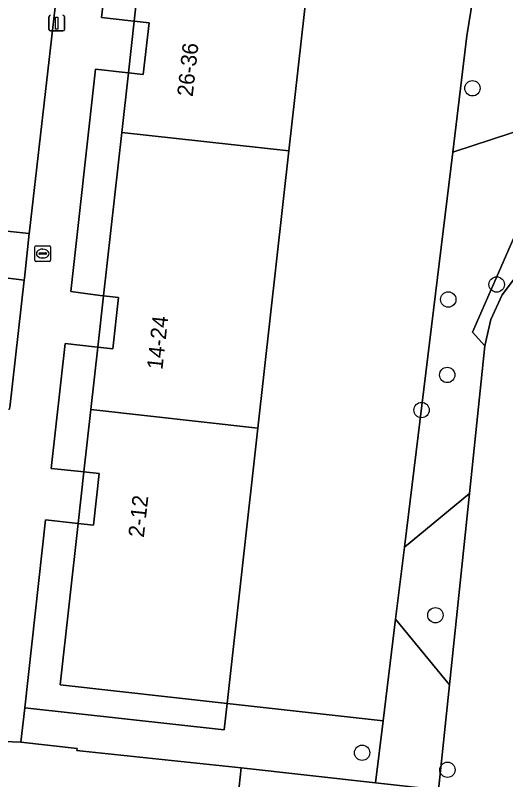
# Model space of a CAD drawing. Extents: x 161928 to 163071, y 386474 to 387428.
# Drawn here: x 162391.2 to 162422.4, y 386658.51 to 386707.21 of the extents above; entities that cross this region are included whole.
import ezdxf

# ---------------------------------------------------------------- set-up
doc = ezdxf.new("R2010")
doc.units = 0
for name, color, linetype in [('IMGEO_Boom', 7, 'Continuous'), ('IMGEO_Groenvoorziening', 7, 'Continuous'), ('IMGEO_Haag', 7, 'Continuous'), ('IMGEO_Hek', 7, 'Continuous'), ('IMGEO_Lichtmast', 7, 'Continuous'), ('IMGEO_Pand', 7, 'Continuous'), ('IMGEO_Pand_nummerreeks', 7, 'Continuous'), ('IMGEO_Rioolput', 7, 'Continuous'), ('IMGEO_Voetpad_open', 7, 'Continuous')]:
    doc.layers.add(name, color=color, linetype=linetype)

msp = doc.modelspace()

# ---------------------------------------------------------------- linework, layer by layer
at = {"layer": 'IMGEO_Boom'}
for centre in [(162420.282, 386702.561), (162421.824, 386690.06), (162418.744, 386689.105), (162418.678, 386684.298), (162417.046, 386682.063), (162417.924, 386668.993), (162413.262, 386660.232), (162418.693, 386659.146)]:
    msp.add_circle(centre, 0.489, dxfattribs=at)
at = {"layer": 'IMGEO_Groenvoorziening'}
for points in [[(162406.78, 386723.545), (162406.356, 386723.597), (162406.309, 386720.802), (162400.545, 386721.503), (162399.908, 386718.167), (162397.924, 386718.328), (162397.858, 386717.736), (162399.847, 386717.48), (162399.793, 386717.072), (162397.894, 386717.26), (162396.674, 386707.06), (162398.541, 386706.853), (162398.76, 386706.829), (162399.934, 386717.343), (162410.567, 386716.163), (162410.886, 386717.317)], [(162352.777, 386665.208), (162379.825, 386662.147), (162388.389, 386661.027), (162389.998, 386674.427), (162390.523, 386679.138), (162387.254, 386679.443), (162387.662, 386682.49), (162390.842, 386682.113), (162390.855, 386682.231), (162391.768, 386690.344), (162388.542, 386690.74), (162388.84, 386693.641), (162392.088, 386693.312), (162392.104, 386693.458), (162393.726, 386707.73), (162390.491, 386708.162), (162390.827, 386711.133), (162394.064, 386710.734), (162394.079, 386710.869), (162394.818, 386717.477), (162394.878, 386718.02), (162395.081, 386719.869), (162368.417, 386722.87)], [(162420.654, 386716.567), (162420.498, 386714.935), (162421.239, 386714.038), (162419.929, 386705.897), (162419.025, 386698.487), (162426.348, 386700.9), (162429.914, 386702.07), (162433.117, 386699.61), (162438.957, 386702.466), (162432.043, 386707.794), (162422.621, 386715.119)], [(162423.214, 386690.791), (162422.18, 386689.408), (162421.457, 386687.841), (162421.075, 386686.157), (162420.097, 386676.753), (162418.828, 386664.56), (162418.132, 386657.869), (162419.347, 386657.734), (162420.414, 386657.578), (162422.602, 386657.107)]]:
    msp.add_lwpolyline(points, dxfattribs=at)
for points in [[(162415.956, 386673.335), (162419.025, 386698.487), (162419.929, 386705.897), (162421.239, 386714.038), (162420.498, 386714.935), (162420.226, 386715.189), (162418.617, 386715.556), (162410.886, 386717.317), (162410.567, 386716.163), (162408.604, 386698.572), (162406.633, 386680.906), (162404.676, 386663.37), (162414.605, 386662.262), (162415.396, 386668.743)], [(162398.177, 386703.573), (162396.31, 386703.78), (162394.738, 386689.606), (162396.605, 386689.37), (162396.809, 386689.348), (162397.97, 386699.752), (162398.394, 386703.549)], [(162437.546, 386696.206), (162433.117, 386699.61), (162429.914, 386702.07), (162426.348, 386700.9), (162420.287, 386687.019), (162421.075, 386686.157), (162421.457, 386687.841), (162422.18, 386689.408), (162423.214, 386690.791), (162424.287, 386691.764), (162425.906, 386693.035), (162427.649, 386694.129), (162429.298, 386694.949), (162430.16, 386695.161), (162431.489, 386695.133), (162432.342, 386694.885), (162433.316, 386694.327), (162435.514, 386694.772)], [(162420.097, 386676.753), (162421.075, 386686.157), (162420.287, 386687.019), (162426.348, 386700.9), (162419.025, 386698.487), (162415.956, 386673.335)], [(162396.243, 386686.09), (162394.371, 386686.297), (162393.489, 386678.347), (162395.362, 386678.139), (162395.556, 386678.118), (162395.999, 386682.093), (162396.443, 386686.068)], [(162418.828, 386664.56), (162420.097, 386676.753), (162415.956, 386673.335), (162415.396, 386668.743)], [(162395, 386674.859), (162393.125, 386675.067), (162391.797, 386663.097), (162404.487, 386661.681), (162404.676, 386663.37), (162394.042, 386664.557), (162395.19, 386674.838)], [(162418.132, 386657.869), (162418.828, 386664.56), (162415.396, 386668.743), (162414.605, 386662.262), (162414.123, 386658.314)], [(162414.605, 386662.262), (162404.676, 386663.37), (162404.487, 386661.681), (162391.797, 386663.097), (162391.553, 386660.896), (162395.131, 386660.509), (162395.102, 386660.372), (162395.484, 386660.338), (162405.564, 386659.264), (162414.123, 386658.314)]]:
    msp.add_lwpolyline(points, close=True, dxfattribs=at)
at = {"layer": 'IMGEO_Haag'}
for points in [[(162398.177, 386703.573), (162396.31, 386703.78), (162394.738, 386689.606), (162396.605, 386689.37), (162396.809, 386689.348), (162397.97, 386699.752), (162398.394, 386703.549)], [(162396.243, 386686.09), (162394.371, 386686.297), (162393.489, 386678.347), (162395.362, 386678.139), (162395.556, 386678.118), (162395.999, 386682.093), (162396.443, 386686.068)], [(162395, 386674.859), (162393.125, 386675.067), (162391.797, 386663.097), (162404.487, 386661.681), (162404.676, 386663.37), (162394.042, 386664.557), (162395.19, 386674.838)]]:
    msp.add_lwpolyline(points, close=True, dxfattribs=at)
at = {"layer": 'IMGEO_Hek'}
for points in [[(162415.956, 386673.335), (162419.025, 386698.487)], [(162415.396, 386668.743), (162415.956, 386673.335)], [(162414.605, 386662.262), (162415.396, 386668.743)], [(162404.676, 386663.37), (162414.605, 386662.262)]]:
    msp.add_lwpolyline(points, dxfattribs=at)
at = {"layer": 'IMGEO_Lichtmast'}
for p, q in [((162393.339, 386706.311), (162393.339, 386707.111)), ((162393.339, 386707.111), (162393.339, 386706.311)), ((162394.329, 386707.111), (162394.329, 386706.311)), ((162394.329, 386706.311), (162394.329, 386707.111)), ((162394.229, 386706.211), (162393.439, 386706.211)), ((162393.439, 386706.211), (162394.229, 386706.211))]:
    msp.add_line(p, q, dxfattribs=at)
msp.add_lwpolyline([(162393.759, 386707.086), (162393.909, 386707.086), (162393.909, 386706.336), (162393.759, 386706.336), (162393.759, 386707.086)], dxfattribs=at)
for centre, start, end in [((162393.439, 386707.111), 90, 180), ((162393.439, 386707.111), 90, 180), ((162394.229, 386707.111), 0, 90), ((162394.229, 386707.111), 360, 90), ((162393.439, 386706.311), 180, 270), ((162393.439, 386706.311), 180, 270), ((162394.229, 386706.311), 270, 0), ((162394.229, 386706.311), 270, 0)]:
    msp.add_arc(centre, 0.1, start, end, dxfattribs=at)
at = {"layer": 'IMGEO_Pand'}
for points in [[(162397.97, 386699.752), (162408.604, 386698.572), (162410.567, 386716.163), (162399.934, 386717.343), (162398.76, 386706.829), (162399.704, 386706.725), (162399.341, 386703.445), (162398.394, 386703.549)], [(162408.604, 386698.572), (162397.97, 386699.752), (162396.809, 386689.348), (162397.769, 386689.242), (162397.406, 386685.962), (162396.443, 386686.068), (162395.999, 386682.093), (162406.633, 386680.906)], [(162406.633, 386680.906), (162395.999, 386682.093), (162395.556, 386678.118), (162396.526, 386678.011), (162396.163, 386674.731), (162395.19, 386674.838), (162394.042, 386664.557), (162404.676, 386663.37)]]:
    msp.add_lwpolyline(points, close=True, dxfattribs=at)
at = {"layer": 'IMGEO_Rioolput'}
for p, q in [((162392.442, 386691.605), (162392.442, 386692.457)), ((162392.517, 386692.531), (162393.369, 386692.531)), ((162393.443, 386692.457), (162393.443, 386691.605)), ((162392.701, 386692.025), (162392.701, 386692.037)), ((162393.139, 386691.988), (162392.741, 386691.988)), ((162392.744, 386692.074), (162393.142, 386692.074)), ((162392.93, 386692.311), (162392.955, 386692.311)), ((162393.185, 386692.037), (162393.185, 386692.025)), ((162393.369, 386691.531), (162392.517, 386691.531)), ((162392.953, 386691.751), (162392.928, 386691.751))]:
    msp.add_line(p, q, dxfattribs=at)
for points in [[(162392.442, 386691.605), (162392.442, 386692.457)], [(162392.517, 386692.531), (162393.369, 386692.531)], [(162393.443, 386692.457), (162393.443, 386691.605)], [(162393.369, 386691.531), (162392.517, 386691.531)]]:
    msp.add_lwpolyline(points, dxfattribs=at)
for centre, radius, start, end in [((162392.519, 386692.455), 0.0765, 91.552, 178.448), ((162392.519, 386692.455), 0.0765, 91.552, 178.448), ((162393.367, 386692.455), 0.0765, 1.552, 88.448), ((162393.367, 386692.455), 0.0765, 1.552, 88.448), ((162392.741, 386692.034), 0.0403, 85.8775, 175.7526), ((162392.738, 386692.024), 0.0366, 178.938, 274.7102), ((162393.142, 386692.031), 0.043, 264.8664, 352.4533), ((162393.146, 386692.036), 0.0386, 1.7309, 96.639), ((162392.519, 386691.607), 0.0765, 181.552, 268.448), ((162392.519, 386691.607), 0.0765, 181.552, 268.448), ((162393.367, 386691.607), 0.0765, 271.552, 358.448), ((162393.367, 386691.607), 0.0765, 271.552, 358.448)]:
    msp.add_arc(centre, radius, start, end, dxfattribs=at)
for centre, major_axis, ratio, start_param, end_param in [((162392.929, 386692.031), (-0.387, 0.002), 0.722429, 4.712389, 7.853982), ((162392.954, 386692.031), (-0.39, 0.002), 0.717154, 1.570796, 4.712389)]:
    msp.add_ellipse(centre, major_axis=major_axis, ratio=ratio, start_param=start_param, end_param=end_param, dxfattribs=at)
at = {"layer": 'IMGEO_Voetpad_open'}
for points in [[(162388.389, 386661.027), (162391.553, 386660.896), (162391.797, 386663.097), (162393.125, 386675.067), (162395, 386674.859), (162395.19, 386674.838), (162395.556, 386678.118), (162395.362, 386678.139), (162393.489, 386678.347), (162394.371, 386686.297), (162396.243, 386686.09), (162396.443, 386686.068), (162396.809, 386689.348), (162396.605, 386689.37), (162394.738, 386689.606), (162396.31, 386703.78), (162398.177, 386703.573), (162398.394, 386703.549), (162398.76, 386706.829), (162398.541, 386706.853), (162396.674, 386707.06), (162397.894, 386717.26)], [(162393.726, 386707.73), (162392.104, 386693.458), (162392.088, 386693.312), (162391.783, 386690.473), (162391.768, 386690.344), (162390.855, 386682.231)], [(162405.257, 386656.292), (162405.564, 386659.264), (162395.484, 386660.338), (162395.102, 386660.372), (162395.131, 386660.509), (162391.553, 386660.896), (162388.389, 386661.027), (162379.825, 386662.147), (162352.777, 386665.208), (162348.84, 386665.689), (162345.614, 386665.927), (162340.891, 386666.503), (162325.646, 386668.198), (162310.4, 386669.893), (162306.164, 386670.355), (162303.013, 386670.566), (162298.443, 386671.239), (162265.931, 386674.909)], [(162422.602, 386657.107), (162420.414, 386657.578), (162419.347, 386657.734), (162418.132, 386657.869), (162414.123, 386658.314), (162405.564, 386659.264), (162405.257, 386656.292), (162418.483, 386654.813), (162420.192, 386654.565), (162422.714, 386654.003)]]:
    msp.add_lwpolyline(points, dxfattribs=at)
for points in [[(162398.394, 386703.549), (162399.341, 386703.445), (162399.704, 386706.725), (162398.76, 386706.829)], [(162392.088, 386693.312), (162388.84, 386693.641), (162388.542, 386690.74), (162391.768, 386690.344), (162391.783, 386690.473)], [(162396.443, 386686.068), (162397.406, 386685.962), (162397.769, 386689.242), (162396.809, 386689.348)], [(162395.19, 386674.838), (162396.163, 386674.731), (162396.526, 386678.011), (162395.556, 386678.118)]]:
    msp.add_lwpolyline(points, close=True, dxfattribs=at)

# ---------------------------------------------------------------- texts
at = {"layer": 'IMGEO_Pand_nummerreeks'}
for s, p in [('26-36', (162402.481, 386701.995)), ('14-24', (162400.556, 386684.603)), ('2-12', (162399.373, 386673.914))]:
    msp.add_text(s, height=1, rotation=83.6847, dxfattribs=at).set_placement(p)

doc.saveas('drawing.dxf')
